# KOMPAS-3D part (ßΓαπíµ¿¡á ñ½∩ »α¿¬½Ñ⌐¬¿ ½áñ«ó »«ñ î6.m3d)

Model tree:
1. Эскиз:1
2. Операция выдавливания:1
     Расстояние 1 = 12
3. Эскиз:2
4. Вырезать элемент выдавливания:1
     Расстояние 1 = 20
5. Эскиз:3
6. Вырезать элемент выдавливания:2
     Расстояние 1 = 5
7. Скругление:1
     Радиус = 7
8. Скругление:2
     Радиус = 7
9. Скругление:3
     Радиус = 13
